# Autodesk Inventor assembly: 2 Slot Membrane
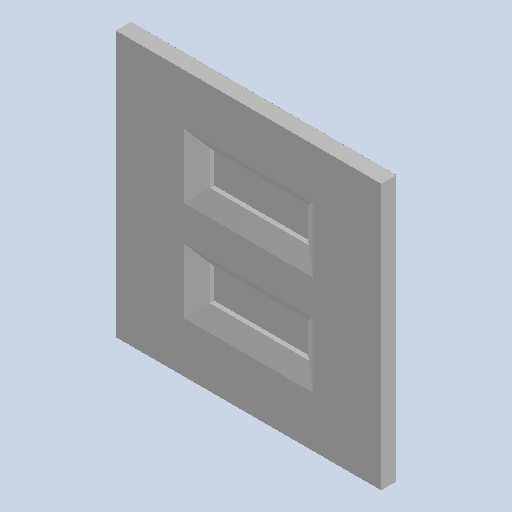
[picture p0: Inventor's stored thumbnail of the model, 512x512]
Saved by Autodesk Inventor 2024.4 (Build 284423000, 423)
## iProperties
Created: 2025-08
Part Number: 2 Slot Membrane
Document SubType Name: Assembly
Designer: AdminForWorker
Title: 2 Slot Membrane v2
Author: AdminForWorker
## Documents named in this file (3)
- c:\worker\convert-fusion-r04-cosv3\tmp\job-1\24\temp\files\cf4e1903-fe1a-4703-ae22-18bcff34d779\c95ef12e-a3a2-4dde-a93c-d27dd1ac7b1b.iam
- c:\worker\convert-fusion-r04-cosv3\tmp\job-1\24\temp\files\cf4e1903-fe1a-4703-ae22-18bcff34d779\Pore Layer.ipt
- c:\worker\convert-fusion-r04-cosv3\tmp\job-1\24\temp\files\cf4e1903-fe1a-4703-ae22-18bcff34d779\2 Slot Membrane.ipt
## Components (2 placed, 2 different names)
1. Pore Layer:1
2. 2 Slot Membrane:1
